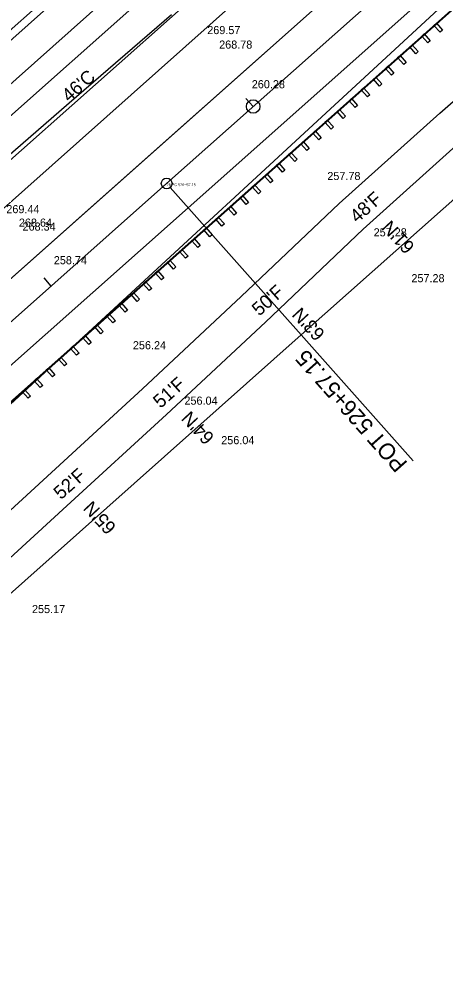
# Model space of a CAD drawing. Extents: x 49683 to 58852, y 49525 to 54803.
# Drawn here: x 54127.1 to 54284.8, y 51788.8 to 52139.1 of the extents above; entities that cross this region are included whole.
import ezdxf

# ---------------------------------------------------------------- set-up
doc = ezdxf.new("R2010")
doc.units = 0
for name, color, linetype in [('Level 1', 7, 'Continuous'), ('Level 11', 7, 'Continuous'), ('Level 13', 7, 'Continuous'), ('Level 18', 7, 'Continuous'), ('Level 19', 7, 'Continuous'), ('Level 20', 7, 'Continuous'), ('Level 27', 7, 'Continuous'), ('Level 3', 7, 'Continuous'), ('Level 32', 7, 'Continuous'), ('Level 33', 7, 'Continuous'), ('Level 48', 7, 'Continuous'), ('Level 51', 7, 'Continuous'), ('Level 8', 7, 'Continuous')]:
    doc.layers.add(name, color=color, linetype=linetype)

msp = doc.modelspace()

# ---------------------------------------------------------------- linework, layer by layer
at = {"layer": 'Level 1'}
msp.add_line((52544.81, 50683.3), (55534.58, 53340.86), dxfattribs=at)
at = {"layer": 'Level 11'}
for p, q in [((53944.24, 51830.77), (54450.3, 52297.6)), ((53894.91, 51911.93), (54324.2, 52292.62))]:
    msp.add_line(p, q, dxfattribs=at)
at = {"layer": 'Level 13'}
for p, q in [((55279.53, 53070), (53969.03, 51905.11)), ((54971.79, 52884.76), (53925.18, 51954.44))]:
    msp.add_line(p, q, dxfattribs=at)
at = {"layer": 'Level 18'}
for p, q in [((54145.7, 52107.97), (54183.54, 52140.66)), ((54282.84, 52104.2), (54320.49, 52137.11)), ((54107.86, 52075.28), (54145.7, 52107.97)), ((54245.68, 52070.75), (54282.84, 52104.2)), ((54254.51, 52061.2), (54291.47, 52094.48)), ((54209.41, 52036.3), (54245.68, 52070.75)), ((54218.32, 52026.84), (54254.51, 52061.2)), ((54172.86, 52002.16), (54209.41, 52036.3)), ((54181.69, 51992.62), (54218.32, 52026.84)), ((54136.01, 51968.35), (54172.86, 52002.16)), ((54144.79, 51958.76), (54181.69, 51992.62)), ((54099.1, 51934.61), (54136.01, 51968.35)), ((54107.84, 51924.98), (54144.79, 51958.76))]:
    msp.add_line(p, q, dxfattribs=at)
at = {"layer": 'Level 19'}
for p, q in [((54181.77, 52078.16), (56150.85, 53828.45)), ((54213.79, 52106.63), (54211.13, 52109.62)), ((52714.15, 50773.62), (54181.77, 52078.16)), ((54273, 51975.52), (54183.1, 52076.67)), ((54139.05, 52040.19), (54136.39, 52043.18))]:
    msp.add_line(p, q, dxfattribs=at)
for centre, radius in [((54213.79, 52106.63), 2.5), ((54181.77, 52078.16), 2)]:
    msp.add_circle(centre, radius, dxfattribs=at)
at = {"layer": 'Level 20'}
for p, q in [((54173.8, 52087.13), (55269.45, 53061.04)), ((54189.74, 52069.19), (55278.86, 53037.3)), ((53930.77, 51871.11), (54173.8, 52087.13)), ((53946.72, 51853.17), (54189.74, 52069.19))]:
    msp.add_line(p, q, dxfattribs=at)
at = {"layer": 'Level 27'}
for p, q in [((54196.38, 52061.72), (54970.77, 52750.06)), ((54196.55, 52061.53), (54970.94, 52749.87)), ((54280.73, 52136.69), (54281.61, 52137.47)), ((54281.61, 52137.47), (54283.87, 52134.93)), ((54282.99, 52134.15), (54280.73, 52136.69)), ((54283.87, 52134.93), (54282.99, 52134.15)), ((54276.24, 52132.7), (54277.13, 52133.49)), ((54278.5, 52130.16), (54276.24, 52132.7)), ((54277.13, 52133.49), (54279.38, 52130.95)), ((54279.38, 52130.95), (54278.5, 52130.16)), ((54271.76, 52128.72), (54272.64, 52129.5)), ((54274.02, 52126.17), (54271.76, 52128.72)), ((54272.64, 52129.5), (54274.9, 52126.96)), ((54274.9, 52126.96), (54274.02, 52126.17)), ((54267.27, 52124.73), (54268.16, 52125.51)), ((54269.53, 52122.19), (54267.27, 52124.73)), ((54268.16, 52125.51), (54270.42, 52122.97)), ((54262.79, 52120.74), (54263.67, 52121.53)), ((54265.05, 52118.2), (54262.79, 52120.74)), ((54263.67, 52121.53), (54265.93, 52118.99)), ((54270.42, 52122.97), (54269.53, 52122.19)), ((54258.3, 52116.76), (54259.19, 52117.54)), ((54260.56, 52114.22), (54258.3, 52116.76)), ((54259.19, 52117.54), (54261.45, 52115)), ((54265.93, 52118.99), (54265.05, 52118.2)), ((54253.82, 52112.77), (54254.7, 52113.56)), ((54254.7, 52113.56), (54256.96, 52111.01)), ((54261.45, 52115), (54260.56, 52114.22)), ((54249.34, 52108.78), (54250.22, 52109.57)), ((54250.22, 52109.57), (54252.48, 52107.03)), ((54256.08, 52110.23), (54253.82, 52112.77)), ((54256.96, 52111.01), (54256.08, 52110.23)), ((54251.59, 52106.24), (54249.34, 52108.78)), ((54252.48, 52107.03), (54251.59, 52106.24)), ((54244.85, 52104.8), (54245.73, 52105.58)), ((54247.11, 52102.26), (54244.85, 52104.8)), ((54245.73, 52105.58), (54247.99, 52103.04)), ((54247.99, 52103.04), (54247.11, 52102.26)), ((54240.37, 52100.81), (54241.25, 52101.6)), ((54242.62, 52098.27), (54240.37, 52100.81)), ((54241.25, 52101.6), (54243.51, 52099.06)), ((54243.51, 52099.06), (54242.62, 52098.27)), ((54235.88, 52096.83), (54236.77, 52097.61)), ((54238.14, 52094.28), (54235.88, 52096.83)), ((54236.77, 52097.61), (54239.02, 52095.07)), ((54231.4, 52092.84), (54232.28, 52093.63)), ((54233.66, 52090.3), (54231.4, 52092.84)), ((54232.28, 52093.63), (54234.54, 52091.08)), ((54239.02, 52095.07), (54238.14, 52094.28)), ((54226.91, 52088.85), (54227.8, 52089.64)), ((54229.17, 52086.31), (54226.91, 52088.85)), ((54227.8, 52089.64), (54230.06, 52087.1)), ((54234.54, 52091.08), (54233.66, 52090.3)), ((54222.43, 52084.87), (54223.31, 52085.65)), ((54224.69, 52082.33), (54222.43, 52084.87)), ((54223.31, 52085.65), (54225.57, 52083.11)), ((54230.06, 52087.1), (54229.17, 52086.31)), ((54217.94, 52080.88), (54218.83, 52081.67)), ((54218.83, 52081.67), (54221.09, 52079.13)), ((54225.57, 52083.11), (54224.69, 52082.33)), ((54220.2, 52078.34), (54217.94, 52080.88)), ((54221.09, 52079.13), (54220.2, 52078.34)), ((54213.46, 52076.9), (54214.34, 52077.68)), ((54215.72, 52074.35), (54213.46, 52076.9)), ((54214.34, 52077.68), (54216.6, 52075.14)), ((54216.6, 52075.14), (54215.72, 52074.35)), ((54208.98, 52072.91), (54209.86, 52073.69)), ((54211.23, 52070.37), (54208.98, 52072.91)), ((54209.86, 52073.69), (54212.12, 52071.15)), ((54212.12, 52071.15), (54211.23, 52070.37)), ((54204.49, 52068.92), (54205.37, 52069.71)), ((54206.75, 52066.38), (54204.49, 52068.92)), ((54205.37, 52069.71), (54207.63, 52067.17)), ((54200.01, 52064.94), (54200.89, 52065.72)), ((54202.26, 52062.4), (54200.01, 52064.94)), ((54200.89, 52065.72), (54203.15, 52063.18)), ((54207.63, 52067.17), (54206.75, 52066.38)), ((53938.41, 51832.41), (54196.38, 52061.72)), ((53938.58, 51832.22), (54196.55, 52061.53)), ((54195.52, 52060.95), (54196.41, 52061.74)), ((54197.78, 52058.41), (54195.52, 52060.95)), ((54196.41, 52061.74), (54198.66, 52059.19)), ((54203.15, 52063.18), (54202.26, 52062.4)), ((54191.04, 52056.96), (54191.92, 52057.75)), ((54193.3, 52054.42), (54191.04, 52056.96)), ((54191.92, 52057.75), (54194.18, 52055.21)), ((54198.66, 52059.19), (54197.78, 52058.41)), ((54186.55, 52052.98), (54187.44, 52053.76)), ((54187.44, 52053.76), (54189.69, 52051.22)), ((54194.18, 52055.21), (54193.3, 52054.42)), ((54182.07, 52048.99), (54182.95, 52049.78)), ((54182.95, 52049.78), (54185.21, 52047.24)), ((54188.81, 52050.44), (54186.55, 52052.98)), ((54189.69, 52051.22), (54188.81, 52050.44)), ((54184.33, 52046.45), (54182.07, 52048.99)), ((54185.21, 52047.24), (54184.33, 52046.45)), ((54177.58, 52045.01), (54178.47, 52045.79)), ((54179.84, 52042.46), (54177.58, 52045.01)), ((54178.47, 52045.79), (54180.73, 52043.25)), ((54180.73, 52043.25), (54179.84, 52042.46)), ((54173.1, 52041.02), (54173.98, 52041.8)), ((54175.36, 52038.48), (54173.1, 52041.02)), ((54173.98, 52041.8), (54176.24, 52039.26)), ((54176.24, 52039.26), (54175.36, 52038.48)), ((54168.62, 52037.03), (54169.5, 52037.82)), ((54170.87, 52034.49), (54168.62, 52037.03)), ((54169.5, 52037.82), (54171.76, 52035.28)), ((54164.13, 52033.05), (54165.01, 52033.83)), ((54166.39, 52030.51), (54164.13, 52033.05)), ((54165.01, 52033.83), (54167.27, 52031.29)), ((54171.76, 52035.28), (54170.87, 52034.49)), ((54159.65, 52029.06), (54160.53, 52029.85)), ((54161.9, 52026.52), (54159.65, 52029.06)), ((54160.53, 52029.85), (54162.79, 52027.3)), ((54167.27, 52031.29), (54166.39, 52030.51)), ((54155.16, 52025.08), (54156.05, 52025.86)), ((54156.05, 52025.86), (54158.3, 52023.32)), ((54162.79, 52027.3), (54161.9, 52026.52)), ((54150.68, 52021.09), (54151.56, 52021.87)), ((54151.56, 52021.87), (54153.82, 52019.33)), ((54157.42, 52022.53), (54155.16, 52025.08)), ((54158.3, 52023.32), (54157.42, 52022.53)), ((54152.94, 52018.55), (54150.68, 52021.09)), ((54153.82, 52019.33), (54152.94, 52018.55)), ((54146.19, 52017.1), (54147.08, 52017.89)), ((54148.45, 52014.56), (54146.19, 52017.1)), ((54147.08, 52017.89), (54149.33, 52015.35)), ((54149.33, 52015.35), (54148.45, 52014.56)), ((54141.71, 52013.12), (54142.59, 52013.9)), ((54143.97, 52010.58), (54141.71, 52013.12)), ((54142.59, 52013.9), (54144.85, 52011.36)), ((54144.85, 52011.36), (54143.97, 52010.58)), ((54137.22, 52009.13), (54138.11, 52009.92)), ((54139.48, 52006.59), (54137.22, 52009.13)), ((54138.11, 52009.92), (54140.37, 52007.37)), ((54132.74, 52005.14), (54133.62, 52005.93)), ((54135, 52002.6), (54132.74, 52005.14)), ((54133.62, 52005.93), (54135.88, 52003.39)), ((54140.37, 52007.37), (54139.48, 52006.59)), ((54128.25, 52001.16), (54129.14, 52001.94)), ((54130.51, 51998.62), (54128.25, 52001.16)), ((54129.14, 52001.94), (54131.4, 51999.4)), ((54135.88, 52003.39), (54135, 52002.6)), ((54131.4, 51999.4), (54130.51, 51998.62))]:
    msp.add_line(p, q, dxfattribs=at)
at = {"layer": 'Level 3'}
for p, q in [((54069.54, 52054.72), (54330.23, 52286.79)), ((54083.39, 52035.12), (54346.38, 52269.23))]:
    msp.add_line(p, q, dxfattribs=at)
at = {"layer": 'Level 33'}
for p, q in [((54231.59, 52022.1), (55608.96, 53246.42)), ((53814.15, 51651.04), (54231.6, 52022.1))]:
    msp.add_line(p, q, dxfattribs=at)
at = {"layer": 'Level 8'}
msp.add_line((54015.78, 52039), (54838.64, 52769.14), dxfattribs=at)

# ---------------------------------------------------------------- texts
at = {"layer": 'Level 19'}
msp.add_text('POT 526+57.15', height=6, rotation=131.6334, dxfattribs=at).set_placement((54271.21, 51974.64))
at = {"layer": 'Level 32'}
for s, p in [('269.57', (54196.8, 52133.44)), ('268.78', (54201.21, 52128.07)), ('260.28', (54213.29, 52113.4)), ('257.78', (54241.24, 52079.42)), ('269.44', (54122.42, 52067.15)), ('268.64', (54127.06, 52062.16)), ('268.34', (54128.42, 52060.7)), ('257.28', (54258.4, 52058.57)), ('258.74', (54140, 52048.25)), ('257.28', (54272.38, 52041.59)), ('256.24', (54169.28, 52016.77)), ('256.04', (54188.36, 51996.26)), ('256.04', (54201.98, 51981.62)), ('255.17', (54131.92, 51919.1))]:
    msp.add_text(s, height=3, dxfattribs=at).set_placement(p)
at = {"layer": 'Level 48'}
for s, rotation, p in [("46'C", 41.6334, (54145.7, 52107.97)), ("48'F", 41.6334, (54252.33, 52063.27)), ("61'N", 132.8528, (54273.9, 52055)), ("50'F", 41.6334, (54216.05, 52028.82)), ("63'N", 132.8528, (54240.68, 52022.77)), ("51'F", 41.6334, (54179.5, 51994.68)), ("64'N", 132.8528, (54199.72, 51984.36)), ("52'F", 41.6334, (54142.65, 51960.88)), ("65'N", 132.8528, (54163.4, 51951.11))]:
    msp.add_text(s, height=5, rotation=rotation, dxfattribs=at).set_placement(p)
at = {"layer": 'Level 51'}
msp.add_text('26 PC 526+57.15', height=1, dxfattribs=at).set_placement((54181.77, 52077.16))

doc.saveas('drawing.dxf')
